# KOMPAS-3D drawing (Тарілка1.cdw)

Referenced files in D:\1\н\: н2.cdw
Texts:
  ДП.НО-24.00.00.001
  Тарілка
  133 1 134 1 135 1 136 0 50 1|SPDS|133 1 134 1 135 1 136 0 50 1
  125 1 126 1 127 1 128 0 50 1|SPDS|125 1 126 1 127 1 128 0 50 1
  129 1 130 1 131 1 132 0 50 1|SPDS|129 1 130 1 131 1 132 0 50 1
  1. Биття поверхонь А, Б, В, Г відносно спільної осі не більше
  2.  Невказані граничні відхилення h 14 +/-ІТ14/2.
  Лавров
  Лівак
  Реценз.
  НОк-98-3
  ІФНТУНГ
  Сталь20Х
  ГОСТ4543-71
  Шостаківський
  Крижанівський
  ДП.НО-24.00.00.001-
Dimensions and other numbers on the sheet: 78*; 0,63; 2; 2 фаски; 20; 30; 106; 80; 0.63; 0,03 мм.; 3,2; 2,6; 2:1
